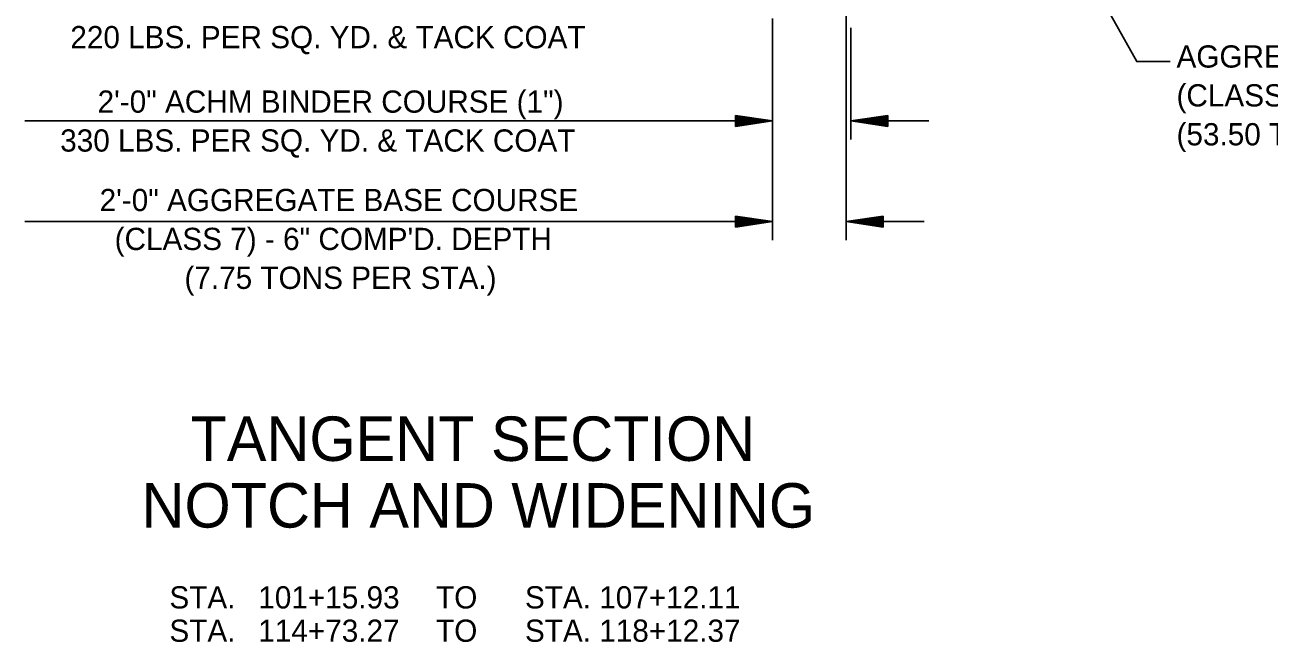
# Model space of a CAD drawing. Extents: x -900 to 15312, y 1857 to 2945.
# Drawn here: x -581.2 to -245.2, y 1995.2 to 2161.8 of the extents above; entities that cross this region are included whole.
import ezdxf

# ---------------------------------------------------------------- set-up
doc = ezdxf.new("R2010")
doc.units = 0
doc.layers.add('R_Annotation', color=7, linetype='Continuous')
doc.layers.add('R_Dimension', color=7, linetype='Continuous')

msp = doc.modelspace()

# ---------------------------------------------------------------- linework, layer by layer
at = {"layer": 'R_Dimension'}
for p, q in [((-359.44, 2103.75), (-359.44, 2200.09)), ((-379.31, 2108.75), (-379.31, 2163.57)), ((-358.18, 2130.91), (-358.18, 2161.07)), ((-389.31, 2137.41), (-379.31, 2135.91)), ((-389.31, 2134.41), (-389.31, 2137.41)), ((-389.31, 2137.16), (-380.98, 2135.91)), ((-389.31, 2136.9), (-382.7, 2135.91)), ((-348.18, 2137.41), (-358.18, 2135.91)), ((-348.18, 2137.16), (-356.51, 2135.91)), ((-348.18, 2136.9), (-354.79, 2135.91)), ((-348.18, 2134.41), (-348.18, 2137.41)), ((-581.18, 2135.91), (-379.31, 2135.91)), ((-389.31, 2136.65), (-384.36, 2135.91)), ((-389.31, 2136.4), (-386.06, 2135.91)), ((-389.31, 2136.14), (-387.73, 2135.91)), ((-389.31, 2134.41), (-379.31, 2135.91)), ((-389.31, 2135.42), (-386.06, 2135.91)), ((-389.31, 2134.91), (-382.7, 2135.91)), ((-389.31, 2134.66), (-380.98, 2135.91)), ((-389.31, 2135.16), (-384.36, 2135.91)), ((-389.31, 2135.67), (-387.73, 2135.91)), ((-348.18, 2134.41), (-358.18, 2135.91)), ((-358.18, 2135.91), (-337.09, 2135.91)), ((-348.18, 2134.66), (-356.51, 2135.91)), ((-348.18, 2134.91), (-354.79, 2135.91)), ((-348.18, 2136.65), (-353.12, 2135.91)), ((-348.18, 2135.16), (-353.12, 2135.91)), ((-348.18, 2136.4), (-351.43, 2135.91)), ((-348.18, 2135.42), (-351.43, 2135.91)), ((-348.18, 2136.14), (-349.76, 2135.91)), ((-348.18, 2135.67), (-349.76, 2135.91)), ((-389.31, 2110.25), (-379.31, 2108.75)), ((-389.31, 2107.25), (-389.31, 2110.25)), ((-389.31, 2110), (-380.98, 2108.75)), ((-349.44, 2110.25), (-359.44, 2108.75)), ((-349.44, 2110), (-357.77, 2108.75)), ((-349.44, 2107.25), (-349.44, 2110.25)), ((-581.18, 2108.75), (-379.31, 2108.75)), ((-389.31, 2109.75), (-382.7, 2108.75)), ((-389.31, 2109.5), (-384.36, 2108.75)), ((-389.31, 2109.24), (-386.06, 2108.75)), ((-389.31, 2108.99), (-387.73, 2108.75)), ((-389.31, 2107.25), (-379.31, 2108.75)), ((-389.31, 2108.27), (-386.06, 2108.75)), ((-389.31, 2107.76), (-382.7, 2108.75)), ((-389.31, 2107.5), (-380.98, 2108.75)), ((-389.31, 2108.01), (-384.36, 2108.75)), ((-389.31, 2108.52), (-387.73, 2108.75)), ((-379.31, 2103.75), (-379.31, 2108.75)), ((-349.44, 2107.25), (-359.44, 2108.75)), ((-359.44, 2108.75), (-338.36, 2108.75)), ((-349.44, 2107.5), (-357.77, 2108.75)), ((-349.44, 2109.75), (-356.05, 2108.75)), ((-349.44, 2107.76), (-356.05, 2108.75)), ((-349.44, 2109.5), (-354.39, 2108.75)), ((-349.44, 2108.01), (-354.39, 2108.75)), ((-349.44, 2109.24), (-352.69, 2108.75)), ((-349.44, 2108.27), (-352.69, 2108.75)), ((-349.44, 2108.99), (-351.02, 2108.75)), ((-349.44, 2108.52), (-351.02, 2108.75))]:
    msp.add_line(p, q, dxfattribs=at)
msp.add_lwpolyline([(-271.95, 2151.92), (-280.94, 2151.92), (-315.09, 2212.99)], dxfattribs=at)

# ---------------------------------------------------------------- texts
at = {"layer": 'R_Annotation'}
for s, height, p in [('220 LBS. PER SQ. YD. & TACK COAT', 6, (-568.9, 2155.54)), ('AGGREGATE BASE COURSE', 6, (-270.21, 2150.32)), ('2\'-0" ACHM BINDER COURSE (1")', 6, (-561.55, 2138.14)), ("(CLASS 7) - VAR. COMP'D. DEPTH", 6, (-270.21, 2139.82)), ('330 LBS. PER SQ. YD. & TACK COAT', 6, (-571.64, 2127.64)), ('(53.50 TONS PER STA.)', 6, (-270.21, 2129.32)), ('2\'-0" AGGREGATE BASE COURSE', 6, (-561, 2111.57)), ('(CLASS 7) - 6" COMP\'D. DEPTH', 6, (-556.94, 2101.07)), ('(7.75 TONS PER STA.)', 6, (-538.09, 2090.57)), ('TANGENT SECTION', 12, (-536.45, 2044.13)), ('NOTCH AND WIDENING', 12, (-549.67, 2026.13)), ('STA. ', 6, (-542.15, 2004.3)), ('101+15.93 ', 6, (-518.15, 2004.3)), ('TO ', 6, (-470.15, 2004.3)), ('STA. 107+12.11', 6, (-446.15, 2004.3)), ('STA. ', 6, (-542.15, 1995.3)), ('114+73.27 ', 6, (-518.15, 1995.3)), ('TO ', 6, (-470.15, 1995.3)), ('STA. 118+12.37', 6, (-446.15, 1995.3))]:
    msp.add_text(s, height=height, dxfattribs=at).set_placement(p)

doc.saveas('drawing.dxf')
